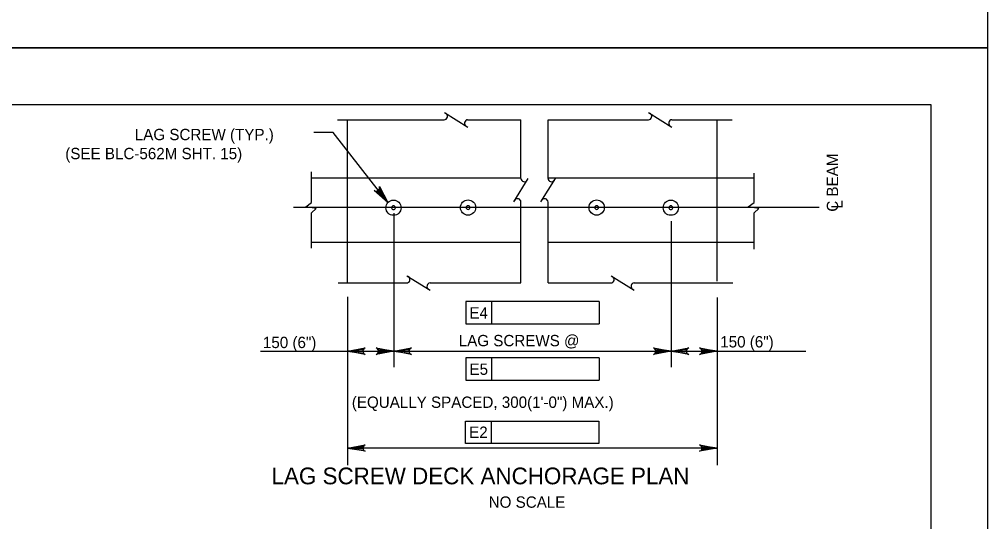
# Model space of a CAD drawing. Extents: x 638263 to 640360, y 293683 to 298655.
# Drawn here: x 639861.3 to 640117.5, y 295934.1 to 296067 of the extents above; entities that cross this region are included whole.
import ezdxf

# ---------------------------------------------------------------- set-up
doc = ezdxf.new("R2010")
doc.units = 0
for name, color, linetype in [('2', 7, 'Continuous'), ('3', 7, 'Continuous'), ('4', 7, 'Continuous'), ('8', 7, 'Continuous'), ('PLT-BNDY', 7, 'Continuous')]:
    doc.layers.add(name, color=color, linetype=linetype)

# ---------------------------------------------------------------- blocks, each defined once
blk = doc.blocks.new('B')
at = {"layer": '3'}
blk.add_circle((0, 0), 0.16, dxfattribs=at)
for start, end in [(0, 180), (180, 0)]:
    blk.add_arc((0, 0), 0.0391, start, end, dxfattribs=at)

msp = doc.modelspace()

# ---------------------------------------------------------------- linework, layer by layer
at = {"layer": '2'}
for p, q in [((639316.46, 296044.46), (640102.46, 296044.46)), ((640102.46, 296044.46), (640102.46, 295480.46)), ((639948.08, 295997.23), (639948.08, 296040.41)), ((640045.92, 295997.69), (640045.92, 296040.41))]:
    msp.add_line(p, q, dxfattribs=at)
at = {"layer": '3'}
for p, q in [((639973.72, 296042.35), (639979.88, 296038.48)), ((640027.75, 296042.35), (640033.91, 296038.48)), ((639945.43, 296040.41), (639973.65, 296040.41)), ((639979.87, 296040.41), (639993.98, 296040.41)), ((639993.98, 296024.83), (639993.98, 296040.41)), ((640001.14, 296040.41), (640027.68, 296040.41)), ((640001.14, 296024.83), (640001.14, 296040.41)), ((640033.9, 296040.41), (640049.86, 296040.41)), ((639938.58, 296018.53), (639938.58, 296026.62)), ((640055.66, 296018.53), (640055.66, 296026.25)), ((639938.58, 296025.06), (639993.98, 296025.06)), ((639992.05, 296018.69), (639995.92, 296024.85)), ((639999.2, 296018.69), (640003.07, 296024.85)), ((640001.14, 296025.06), (640055.66, 296025.06)), ((639937.04, 296017.34), (639938.58, 296018.53)), ((639993.98, 295997.23), (639993.98, 296018.62)), ((640001.14, 295997.23), (640001.14, 296018.62)), ((640054.12, 296017.34), (640055.66, 296018.53)), ((639939.8, 296016.91), (639937.04, 296017.34)), ((639938.58, 296015.82), (639939.8, 296016.91)), ((640056.88, 296016.91), (640054.12, 296017.34)), ((640055.66, 296015.82), (640056.88, 296016.91)), ((639938.58, 296006.4), (639938.58, 296015.82)), ((640055.66, 296006.21), (640055.66, 296015.82)), ((639993.98, 296007.94), (639938.58, 296007.94)), ((640055.66, 296007.94), (640001.14, 296007.94)), ((639963.77, 295999.16), (639969.93, 295995.29)), ((640017.8, 295999.16), (640023.96, 295995.29)), ((639945.64, 295997.23), (639963.7, 295997.23)), ((639969.92, 295997.23), (639993.98, 295997.23)), ((640001.14, 295997.23), (640017.73, 295997.23)), ((640023.95, 295997.23), (640050.07, 295997.23))]:
    msp.add_line(p, q, dxfattribs=at)
for centre, start, end in [((639973.65, 296041.32), 270, 60), ((640027.68, 296041.32), 270, 60), ((639979.95, 296039.51), 95.3286, 237.8672), ((640033.98, 296039.51), 95.3286, 237.8672), ((639994.89, 296024.92), 185.3286, 327.8672), ((640002.04, 296024.92), 185.3286, 327.8672), ((639993.07, 296018.62), 0, 150), ((640000.23, 296018.62), 0, 150), ((639963.7, 295998.14), 270, 60), ((640017.73, 295998.14), 270, 60), ((639970, 295996.32), 95.3286, 237.8672), ((640024.03, 295996.32), 95.3286, 237.8672)]:
    msp.add_arc(centre, 0.909, start, end, dxfattribs=at)
at = {"layer": '4'}
for p, q in [((639944.31, 296037.05), (639939.21, 296037.05)), ((640072.85, 296017.17), (639933.81, 296017.17)), ((639979.35, 295992.31), (639979.35, 295986.4)), ((639986.24, 295992.31), (639979.35, 295992.31)), ((640014.65, 295992.31), (639986.24, 295992.31)), ((639986.24, 295986.4), (639986.24, 295992.31)), ((640014.65, 295992.31), (640014.65, 295986.4)), ((639948.08, 295987.91), (639948.08, 295949.07)), ((640045.92, 295987.91), (640045.92, 295949.07)), ((639979.35, 295986.4), (640014.65, 295986.4)), ((639948.08, 295979.22), (639960.31, 295979.22)), ((640033.69, 295979.22), (640045.92, 295979.22)), ((639979.35, 295977.4), (639979.35, 295971.5)), ((639986.24, 295977.4), (639979.35, 295977.4)), ((639986.24, 295971.5), (639986.24, 295977.4)), ((640014.65, 295977.4), (639986.24, 295977.4)), ((640014.65, 295977.4), (640014.65, 295971.5)), ((639979.35, 295971.5), (640014.65, 295971.5)), ((639979.31, 295960.72), (639986.2, 295960.72)), ((639979.31, 295954.81), (639979.31, 295960.72)), ((639986.2, 295954.81), (639986.2, 295960.72)), ((639986.2, 295960.72), (640014.61, 295960.72)), ((640014.61, 295960.72), (640014.61, 295954.81)), ((640014.61, 295954.81), (639979.31, 295954.81)), ((640045.92, 295953.57), (639948.08, 295953.57))]:
    msp.add_line(p, q, dxfattribs=at)
for points in [[(639958.72, 296018.5), (639944.31, 296037.05)], [(639958.72, 296018.51), (639955.17, 296021.65), (639955.59, 296021.52), (639955.95, 296021.56), (639956.23, 296021.71), (639956.44, 296021.95), (639956.58, 296022.29), (639956.55, 296022.72), (639958.72, 296018.51), (639956.58, 296022.29), (639956.44, 296021.95), (639958.72, 296018.51), (639956.23, 296021.71), (639955.95, 296021.56), (639958.72, 296018.51), (639955.59, 296021.52)], [(639948.08, 295979.22), (639952.74, 295980.1), (639952.38, 295979.85), (639952.2, 295979.54), (639952.14, 295979.22), (639952.2, 295978.91), (639952.38, 295978.6), (639952.74, 295978.35), (639948.08, 295979.22), (639952.38, 295978.6), (639952.2, 295978.91), (639948.08, 295979.22), (639952.14, 295979.22), (639952.2, 295979.54), (639948.08, 295979.22), (639952.38, 295979.85)], [(639960.31, 295979.22), (639955.65, 295978.35), (639956.01, 295978.6), (639956.19, 295978.91), (639956.25, 295979.22), (639956.19, 295979.54), (639956.01, 295979.85), (639955.65, 295980.1), (639960.31, 295979.22), (639956.01, 295979.85), (639956.19, 295979.54), (639960.31, 295979.22), (639956.25, 295979.22), (639956.19, 295978.91), (639960.31, 295979.22), (639956.01, 295978.6)], [(639960.31, 295979.22), (639964.97, 295980.1), (639964.61, 295979.85), (639964.43, 295979.54), (639964.37, 295979.22), (639964.43, 295978.91), (639964.61, 295978.6), (639964.97, 295978.35), (639960.31, 295979.22), (639964.61, 295978.6), (639964.43, 295978.91), (639960.31, 295979.22), (639964.37, 295979.22), (639964.43, 295979.54), (639960.31, 295979.22), (639964.61, 295979.85)], [(640033.69, 295979.22), (640029.03, 295978.35), (640029.39, 295978.6), (640029.57, 295978.91), (640029.63, 295979.22), (640029.57, 295979.54), (640029.39, 295979.85), (640029.03, 295980.1), (640033.69, 295979.22), (640029.39, 295979.85), (640029.57, 295979.54), (640033.69, 295979.22), (640029.63, 295979.22), (640029.57, 295978.91), (640033.69, 295979.22), (640029.39, 295978.6)], [(640033.69, 295979.22), (640038.35, 295980.1), (640037.99, 295979.85), (640037.81, 295979.54), (640037.75, 295979.22), (640037.81, 295978.91), (640037.99, 295978.6), (640038.35, 295978.35), (640033.69, 295979.22), (640037.99, 295978.6), (640037.81, 295978.91), (640033.69, 295979.22), (640037.75, 295979.22), (640037.81, 295979.54), (640033.69, 295979.22), (640037.99, 295979.85)], [(640045.92, 295979.22), (640041.26, 295978.35), (640041.62, 295978.6), (640041.8, 295978.91), (640041.86, 295979.22), (640041.8, 295979.54), (640041.62, 295979.85), (640041.26, 295980.1), (640045.92, 295979.22), (640041.62, 295979.85), (640041.8, 295979.54), (640045.92, 295979.22), (640041.86, 295979.22), (640041.8, 295978.91), (640045.92, 295979.22), (640041.62, 295978.6)], [(639948.08, 295953.57), (639952.74, 295954.44), (639952.38, 295954.19), (639952.2, 295953.88), (639952.14, 295953.57), (639952.2, 295953.26), (639952.38, 295952.94), (639952.74, 295952.7), (639948.08, 295953.57), (639952.38, 295952.94), (639952.2, 295953.26), (639948.08, 295953.57), (639952.14, 295953.57), (639952.2, 295953.88), (639948.08, 295953.57), (639952.38, 295954.19)], [(640045.92, 295953.57), (640041.26, 295952.7), (640041.62, 295952.94), (640041.8, 295953.26), (640041.86, 295953.57), (640041.8, 295953.88), (640041.62, 295954.19), (640041.26, 295954.44), (640045.92, 295953.57), (640041.62, 295954.19), (640041.8, 295953.88), (640045.92, 295953.57), (640041.86, 295953.57), (640041.8, 295953.26), (640045.92, 295953.57), (640041.62, 295952.94)]]:
    msp.add_lwpolyline(points, dxfattribs=at)
at = {"layer": '8'}
for p, q in [((639960.31, 296015.69), (639960.31, 295974.97)), ((640033.69, 296013.61), (640033.69, 295974.97)), ((639948.08, 295993.56), (639948.08, 295974.97)), ((640045.92, 295993.36), (640045.92, 295974.97)), ((639925.02, 295979.22), (639957.48, 295979.22)), ((639960.31, 295979.22), (640033.69, 295979.22)), ((640045.92, 295979.22), (640069.33, 295979.22))]:
    msp.add_line(p, q, dxfattribs=at)
at = {"layer": 'PLT-BNDY'}
for points in [[(639276.46, 296653.46), (640117.46, 296653.46), (640117.46, 296059.46), (639276.46, 296059.46)], [(639276.46, 296059.46), (640117.46, 296059.46), (640117.46, 295465.46), (639276.46, 295465.46)]]:
    msp.add_lwpolyline(points, close=True, dxfattribs=at)

# ---------------------------------------------------------------- block references
at = {"layer": '4', "xscale": 12.59905511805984, "yscale": 12.599055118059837}
for p in [(639960.25, 296017.14), (639979.97, 296017.17), (640014.01, 296017.17), (640033.63, 296017.14)]:
    msp.add_blockref('B', p, dxfattribs=at)

# ---------------------------------------------------------------- texts
at = {"layer": '4'}
for s, height, p in [('LAG SCREW (TYP.)', 3, (639891.8, 296035)), ('(SEE BLC-562M SHT. 15)', 3, (639873.4, 296029.97)), ('E4', 3, (639980.33, 295987.83)), ('150 (6")', 3, (639925.7, 295980.01)), ('LAG SCREWS @', 3, (639977.51, 295980.49)), ('150 (6")', 3, (640046.71, 295980.18)), ('E5', 3, (639980.36, 295972.93)), ('(EQUALLY SPACED, 300(1\'-0") MAX.)', 3, (639949.22, 295964.19)), ('E2', 3, (639980.27, 295956.25)), ('LAG SCREW DECK ANCHORAGE PLAN', 4.4292, (639927.98, 295943.98)), ('NO SCALE', 3, (639985.43, 295937.77))]:
    msp.add_text(s, height=height, dxfattribs=at).set_placement(p)
for s, p in [('C BEAM', (640077.89, 296016.08)), ('L', (640079.09, 296016.92))]:
    msp.add_text(s, height=3, rotation=90, dxfattribs=at).set_placement(p)

doc.saveas('drawing.dxf')
